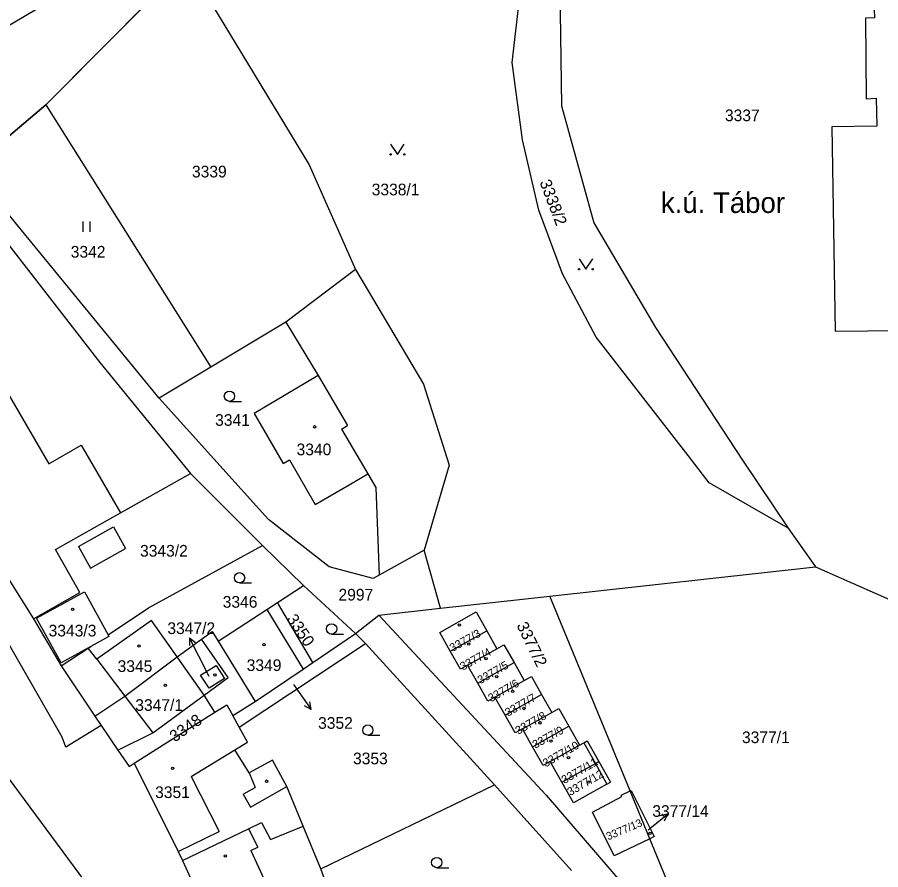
# Model space of a CAD drawing. Extents: x -738085 to -734306, y -1122197 to -1119753.
# Drawn here: x -735120.1 to -734994.5, y -1120373.5 to -1120249.4 of the extents above; entities that cross this region are included whole.
import ezdxf

# ---------------------------------------------------------------- set-up
doc = ezdxf.new("R2010")
doc.units = 0
for name, color, linetype in [('Hranice parcel', 7, 'Continuous'), ('Parcelní čísla', 7, 'Continuous'), ('Pop  PČ popisy', 7, 'Continuous'), ('SŽDC', 7, 'Continuous'), ('Vnitřní kresba', 7, 'Continuous'), ('Vrstva 1', 7, 'Continuous'), ('Vrstva 53', 7, 'Continuous'), ('Značky budov', 7, 'Continuous'), ('Značky kultur', 7, 'Continuous')]:
    doc.layers.add(name, color=color, linetype=linetype)

msp = doc.modelspace()

# ---------------------------------------------------------------- linework, layer by layer
at = {"layer": 'Hranice parcel'}
for p, q in [((-735095.46, -1120241.5), (-735115.98, -1120262.16)), ((-735115.98, -1120262.16), (-735126.91, -1120271.38)), ((-735115.98, -1120262.16), (-735091.96, -1120300.34)), ((-735070.92, -1120286.13), (-735081.05, -1120293.8)), ((-735081.05, -1120293.8), (-735091.96, -1120300.34)), ((-735091.96, -1120300.34), (-735099.51, -1120304.86)), ((-735094.95, -1120315.79), (-735084.44, -1120326.28)), ((-735007.98, -1120323.75), (-735004, -1120329.4)), ((-735084.44, -1120326.28), (-735078.49, -1120332.09)), ((-735060.91, -1120326.97), (-735067.5, -1120330.6)), ((-735058.56, -1120335.42), (-735060.91, -1120326.97)), ((-735042.66, -1120333.67), (-735004, -1120329.4)), ((-735004, -1120329.4), (-734988.44, -1120336.27)), ((-735082.29, -1120334.57), (-735078.49, -1120332.09)), ((-735078.49, -1120332.09), (-735070.91, -1120339.1)), ((-735058.56, -1120335.42), (-735042.66, -1120333.67)), ((-735030.98, -1120361.99), (-735042.66, -1120333.67)), ((-735077.11, -1120343.32), (-735082.29, -1120334.57)), ((-735067.51, -1120336.41), (-735058.56, -1120335.42)), ((-735070.91, -1120339.1), (-735067.51, -1120336.41)), ((-735117.78, -1120336.94), (-735113.76, -1120343.8)), ((-735077.11, -1120343.32), (-735070.91, -1120339.1)), ((-735069.48, -1120340.54), (-735070.91, -1120339.1)), ((-735057.13, -1120341.67), (-735051.83, -1120338.69)), ((-735051.83, -1120338.69), (-735050.36, -1120341.3)), ((-735096.87, -1120342.5), (-735093.34, -1120339.91)), ((-735087.83, -1120352.73), (-735069.48, -1120340.54)), ((-735050.7, -1120361.08), (-735069.48, -1120340.54)), ((-735113.76, -1120343.8), (-735109.82, -1120341.23)), ((-735109.82, -1120341.23), (-735109.44, -1120340.97)), ((-735054.61, -1120343.69), (-735050.36, -1120341.3)), ((-735092.93, -1120348.05), (-735096.87, -1120342.5)), ((-735113.76, -1120343.8), (-735108.84, -1120351.11)), ((-735053.14, -1120346.3), (-735054.61, -1120343.69)), ((-735053.14, -1120346.3), (-735047.84, -1120343.32)), ((-735047.84, -1120343.32), (-735046.37, -1120345.93)), ((-735050.63, -1120348.33), (-735046.37, -1120345.93)), ((-735091.37, -1120350.53), (-735092.93, -1120348.05)), ((-735049.16, -1120350.94), (-735043.86, -1120347.95)), ((-735043.86, -1120347.95), (-735042.38, -1120350.56)), ((-735049.16, -1120350.94), (-735050.63, -1120348.33)), ((-735103.15, -1120357.97), (-735091.37, -1120350.53)), ((-735046.64, -1120352.96), (-735042.38, -1120350.56)), ((-735108.84, -1120351.11), (-735107.92, -1120352.48)), ((-735087.83, -1120352.73), (-735088.77, -1120351.02)), ((-735107.92, -1120352.48), (-735105.51, -1120356.05)), ((-735045.17, -1120355.57), (-735046.64, -1120352.96)), ((-735045.17, -1120355.57), (-735039.87, -1120352.58)), ((-735039.87, -1120352.58), (-735038.32, -1120355.32)), ((-735042.59, -1120357.72), (-735038.32, -1120355.32)), ((-735040.89, -1120360.73), (-735042.59, -1120357.72)), ((-735040.89, -1120360.73), (-735036.02, -1120357.98)), ((-735075.99, -1120373.34), (-735050.7, -1120361.08)), ((-735039.5, -1120373.56), (-735050.7, -1120361.08)), ((-735028.11, -1120368.94), (-735030.98, -1120361.99)), ((-735075.99, -1120373.34), (-735078.55, -1120367.09)), ((-735019.26, -1120390.39), (-735028.11, -1120368.94)), ((-735096.09, -1120372.12), (-735092.98, -1120378.93)), ((-735075.41, -1120374.92), (-735075.99, -1120373.34))]:
    msp.add_line(p, q, dxfattribs=at)
for points in [[(-735007.98, -1120323.75), (-735019.45, -1120317.14), (-735022.52, -1120313.19), (-735035.93, -1120295.95), (-735040.81, -1120286.74), (-735044.27, -1120277.48), (-735046.62, -1120267.24), (-735048.14, -1120256), (-735046.94, -1120245.5), (-735044.72, -1120235.55), (-735040.96, -1120226.43), (-735034.02, -1120215.67), (-735028.14, -1120208.39), (-735021.59, -1120202.89), (-735007.79, -1120195.85)], [(-735008.98, -1120204.76), (-735000.64, -1120199.87), (-734997.94, -1120203.05), (-734997.43, -1120215.84), (-735002.6, -1120215.9), (-735001.92, -1120245.63), (-734995.53, -1120245.59), (-734995.39, -1120249.51), (-734996.74, -1120249.56), (-734996.6, -1120261.29), (-734995.16, -1120261.22), (-734995.08, -1120265.25), (-735001.61, -1120265.38), (-735001.13, -1120295.08), (-734986.97, -1120294.94), (-734982.61, -1120294.19)], [(-735008.98, -1120204.76), (-735028.61, -1120216.64), (-735041.23, -1120241.83), (-735040.97, -1120262.31), (-735036.25, -1120279.32), (-735027.29, -1120294.54), (-735014.62, -1120313.86), (-735007.98, -1120323.75)], [(-735095.46, -1120241.5), (-735077.67, -1120270.9), (-735070.92, -1120286.13)], [(-735138.19, -1120266.43), (-735129.75, -1120274.85), (-735122.53, -1120281.1), (-735108.15, -1120299.66), (-735094.95, -1120315.79)], [(-735099.51, -1120304.86), (-735120.4, -1120279.32), (-735126.91, -1120271.38)], [(-735107.92, -1120352.48), (-735113.07, -1120355.6), (-735113.62, -1120354.14), (-735135.26, -1120316.47), (-735148.73, -1120292.25), (-735156.12, -1120276.6)], [(-735070.92, -1120286.13), (-735061.04, -1120302.82), (-735057.28, -1120314.6), (-735060.91, -1120326.97)], [(-735081.05, -1120293.8), (-735076.37, -1120301.57), (-735085.67, -1120307.08), (-735081.46, -1120314.34), (-735080.54, -1120313.81), (-735076.77, -1120320.3), (-735071.87, -1120317.44), (-735069.13, -1120315.84), (-735067.96, -1120317.82), (-735067.5, -1120330.6)], [(-735067.5, -1120330.6), (-735068.34, -1120331.06), (-735074.75, -1120329.4), (-735083.57, -1120322.52), (-735099.51, -1120304.86)], [(-735117.78, -1120336.94), (-735111.05, -1120333.12), (-735114.58, -1120326.87), (-735105.14, -1120321.54), (-735094.95, -1120315.79)], [(-735106.92, -1120339.28), (-735101.06, -1120335.34), (-735084.44, -1120326.28)], [(-735121.6, -1120330.83), (-735117.78, -1120336.94)], [(-735109.44, -1120340.97), (-735113.77, -1120343.37), (-735117.35, -1120336.84), (-735110.36, -1120333.04), (-735106.92, -1120339.28)], [(-735093.34, -1120339.91), (-735091.78, -1120338.77), (-735090.91, -1120340.19), (-735083.83, -1120335.57), (-735082.29, -1120334.57)], [(-735067.51, -1120336.41), (-735043.2, -1120362.59), (-735019.26, -1120390.39)], [(-735057.13, -1120341.67), (-735058.67, -1120338.93), (-735053.38, -1120335.95), (-735051.83, -1120338.69)], [(-735096.87, -1120342.5), (-735100.62, -1120337.21), (-735108.56, -1120342.84), (-735109.82, -1120341.23)], [(-735106.92, -1120339.28), (-735106.8, -1120339.51), (-735109.44, -1120340.97)], [(-735092.93, -1120348.05), (-735089.44, -1120345.49), (-735093.34, -1120339.91)], [(-735040.76, -1120465.73), (-735061.72, -1120440.92), (-735081.14, -1120416.75), (-735107.98, -1120378.29), (-735135.71, -1120340.76)], [(-735054.61, -1120343.69), (-735055.66, -1120344.28), (-735057.13, -1120341.67)], [(-735050.36, -1120341.3), (-735049.32, -1120340.71), (-735047.84, -1120343.32)], [(-735108.84, -1120351.11), (-735104.5, -1120348.19), (-735096.87, -1120342.5)], [(-735088.77, -1120351.02), (-735085.52, -1120348.97), (-735078.53, -1120344.29), (-735077.11, -1120343.32)], [(-735046.37, -1120345.93), (-735045.33, -1120345.34), (-735043.86, -1120347.95)], [(-735050.63, -1120348.33), (-735051.67, -1120348.91), (-735053.14, -1120346.3)], [(-735105.51, -1120356.05), (-735100.43, -1120353.54), (-735092.93, -1120348.05)], [(-735091.37, -1120350.53), (-735089.64, -1120349.44), (-735088.77, -1120351.02)], [(-735042.38, -1120350.56), (-735041.34, -1120349.97), (-735039.87, -1120352.58)], [(-735046.64, -1120352.96), (-735047.69, -1120353.55), (-735049.16, -1120350.94)], [(-735078.55, -1120367.09), (-735080.91, -1120361.32), (-735082.99, -1120357.5), (-735086.41, -1120359.36), (-735088.49, -1120356), (-735086.65, -1120354.88), (-735087.83, -1120352.73)], [(-735042.59, -1120357.72), (-735043.63, -1120358.31), (-735045.17, -1120355.57)], [(-735038.32, -1120355.32), (-735037.71, -1120354.98), (-735036.02, -1120357.98)], [(-735105.51, -1120356.05), (-735103.85, -1120358.41), (-735103.15, -1120357.97)], [(-735103.15, -1120357.97), (-735096.75, -1120370.79), (-735096.09, -1120372.12)], [(-735036.02, -1120357.98), (-735034.33, -1120360.98), (-735039.2, -1120363.73), (-735040.89, -1120360.73)], [(-735028.11, -1120368.94), (-735033.28, -1120371.43), (-735036.46, -1120365.06), (-735032.18, -1120362.81), (-735032.27, -1120362.62), (-735030.98, -1120361.99)], [(-735030.98, -1120361.99), (-735030.83, -1120361.92), (-735027.48, -1120368.64), (-735028.11, -1120368.94)], [(-735096.09, -1120372.12), (-735086.5, -1120367.51), (-735084.59, -1120366.59), (-735083.3, -1120369.03), (-735078.55, -1120367.09)]]:
    msp.add_lwpolyline(points, dxfattribs=at)
at = {"layer": 'Pop  PČ popisy'}
for p, q in [((-735093.73, -1120342.38), (-735095.09, -1120339.71)), ((-735095.09, -1120339.71), (-735094.19, -1120340.37)), ((-735095.09, -1120339.71), (-735095.08, -1120340.83)), ((-735092.2, -1120345.34), (-735093.73, -1120342.38)), ((-735079.96, -1120346.48), (-735079.11, -1120347.68)), ((-735079.11, -1120347.68), (-735077.39, -1120350.14)), ((-735077.39, -1120350.14), (-735077.55, -1120349.03)), ((-735077.39, -1120350.14), (-735078.37, -1120349.6)), ((-735027.87, -1120367.27), (-735025.54, -1120365.38)), ((-735025.54, -1120365.38), (-735026.63, -1120365.62)), ((-735025.54, -1120365.38), (-735026, -1120366.4)), ((-735028.34, -1120367.65), (-735027.87, -1120367.27))]:
    msp.add_line(p, q, dxfattribs=at)
at = {"layer": 'SŽDC'}
for p, q in [((-735115.98, -1120262.16), (-735095.46, -1120241.5)), ((-735126.91, -1120271.38), (-735115.98, -1120262.16))]:
    msp.add_line(p, q, dxfattribs=at)
at = {"layer": 'Vnitřní kresba'}
for p, q in [((-735127.32, -1120294.17), (-735115.57, -1120314.42)), ((-735076.37, -1120301.57), (-735072.08, -1120308.82)), ((-735072.98, -1120309.35), (-735072.08, -1120308.82)), ((-735072.98, -1120309.35), (-735069.13, -1120315.84)), ((-735115.57, -1120314.42), (-735110.84, -1120311.67)), ((-735110.84, -1120311.67), (-735105.14, -1120321.54)), ((-735111.24, -1120326.41), (-735106.16, -1120323.58)), ((-735106.16, -1120323.58), (-735104.4, -1120326.73)), ((-735111.24, -1120326.41), (-735109.49, -1120329.56)), ((-735109.49, -1120329.56), (-735104.4, -1120326.73)), ((-735083.83, -1120335.57), (-735078.53, -1120344.29)), ((-735090.91, -1120340.19), (-735085.52, -1120348.97)), ((-735108.56, -1120342.84), (-735104.5, -1120348.19)), ((-735093.49, -1120345.15), (-735091.18, -1120343.74)), ((-735091.18, -1120343.74), (-735089.99, -1120345.61)), ((-735092.22, -1120347.02), (-735093.49, -1120345.15)), ((-735089.99, -1120345.61), (-735092.22, -1120347.02)), ((-735104.5, -1120348.19), (-735100.43, -1120353.54)), ((-735037.71, -1120354.98), (-735037.21, -1120354.7)), ((-735037.21, -1120354.7), (-735035.52, -1120357.7)), ((-735094.83, -1120359.87), (-735088.49, -1120356)), ((-735036.02, -1120357.98), (-735035.52, -1120357.7)), ((-735035.52, -1120357.7), (-735033.83, -1120360.7)), ((-735086.41, -1120359.36), (-735085.52, -1120361.47)), ((-735094.83, -1120359.87), (-735090.77, -1120367.87)), ((-735034.33, -1120360.98), (-735033.83, -1120360.7)), ((-735087.26, -1120362.46), (-735085.52, -1120361.47)), ((-735086.2, -1120364.33), (-735080.91, -1120361.32)), ((-735087.26, -1120362.46), (-735086.2, -1120364.33)), ((-735096.75, -1120370.79), (-735090.77, -1120367.87)), ((-735086.5, -1120367.51), (-735085.15, -1120370.19)), ((-735086.17, -1120370.66), (-735085.15, -1120370.19)), ((-735086.17, -1120370.66), (-735084.22, -1120374.85))]:
    msp.add_line(p, q, dxfattribs=at)
at = {"layer": 'Vrstva 1'}
msp.add_lwpolyline([(-735048.63, -1120207.9), (-735071.26, -1120221.19), (-735095.02, -1120235.15), (-735119.18, -1120249.35), (-735123.66, -1120251.99), (-735132.32, -1120257.08), (-735139.95, -1120261.55), (-735146.73, -1120265.54), (-735150.83, -1120267.95), (-735166.13, -1120276.92), (-735184.2, -1120287.53), (-735210.89, -1120303.2), (-735238.62, -1120319.49), (-735239.7, -1120320.12), (-735247.26, -1120324.55), (-735256.8, -1120330.14), (-735273.62, -1120340.02), (-735285.77, -1120347.18), (-735296.08, -1120353.22), (-735304.06, -1120357.75)], dxfattribs=at)
at = {"layer": 'Vrstva 53'}
msp.add_lwpolyline([(-734742.39, -1120198.31), (-734748.46, -1120195.41), (-734799.69, -1120183.7), (-734853.28, -1120170.95), (-734887.03, -1120164.91), (-734913.87, -1120162.91), (-734932.65, -1120163.73), (-734954.75, -1120168.56), (-734977.62, -1120176.17), (-734996.5, -1120184.52), (-735013.84, -1120194.15), (-735022.76, -1120201.89), (-735069.62, -1120231.25), (-735085.17, -1120235.61), (-735095.46, -1120241.5), (-735115.98, -1120262.16), (-735126.91, -1120271.38), (-735136.63, -1120262.8), (-735138.78, -1120260.72), (-735140.3, -1120259.25), (-735154.27, -1120245.72)], dxfattribs=at)
at = {"layer": 'Značky budov'}
for centre in [(-735076.88, -1120309.02), (-735112.08, -1120335.58), (-735055.83, -1120337.86), (-735084.25, -1120340.71), (-735054.44, -1120340.61), (-735102.41, -1120340.91), (-735051.93, -1120342.76), (-735091.39, -1120345.13), (-735050.38, -1120345.36), (-735098.6, -1120346.61), (-735048.06, -1120347.5), (-735046.42, -1120349.99), (-735044.08, -1120352.08), (-735042.49, -1120354.73), (-735039.93, -1120357.14), (-735097.54, -1120358.71), (-735083.86, -1120360.57), (-735037, -1120360.69), (-735028.06, -1120368.14), (-735089.85, -1120371.45)]:
    msp.add_circle(centre, 0.175, dxfattribs=at)
at = {"layer": 'Značky kultur'}
for p, q in [((-735110.54, -1120280.63), (-735110.54, -1120279.13)), ((-735109.54, -1120280.63), (-735109.54, -1120279.13)), ((-735089.27, -1120305.31), (-735087.52, -1120305.31)), ((-735087.8, -1120331.73), (-735086.05, -1120331.73)), ((-735074.4, -1120339.17), (-735072.65, -1120339.17)), ((-735069.13, -1120353.88), (-735067.38, -1120353.88)), ((-735059.11, -1120373.16), (-735057.36, -1120373.16))]:
    msp.add_line(p, q, dxfattribs=at)
for points in [[(-735065.83, -1120267.88), (-735064.83, -1120269.38), (-735063.83, -1120267.88)], [(-735038.4, -1120284.59), (-735037.4, -1120286.09), (-735036.4, -1120284.59)]]:
    msp.add_lwpolyline(points, dxfattribs=at)
for centre, radius in [((-735065.83, -1120269.38), 0.1), ((-735063.83, -1120269.38), 0.1), ((-735038.4, -1120286.09), 0.1), ((-735036.4, -1120286.09), 0.1), ((-735089.27, -1120304.56), 0.75), ((-735087.8, -1120330.98), 0.75), ((-735074.4, -1120338.42), 0.75), ((-735069.13, -1120353.13), 0.75), ((-735059.11, -1120372.41), 0.75)]:
    msp.add_circle(centre, radius, dxfattribs=at)

# ---------------------------------------------------------------- texts
at = {"layer": 'Hranice parcel'}
msp.add_text('k.ú. Tábor', height=3, dxfattribs=at).set_placement((-735026.49, -1120277.9))
at = {"layer": 'Parcelní čísla'}
for s, p in [('3337', (-735017.17, -1120264.55)), ('3339', (-735094.72, -1120272.73)), ('3338/1', (-735068.57, -1120275.34)), ('3342', (-735112.36, -1120284.4)), ('3341', (-735091.35, -1120308.87)), ('3340', (-735079.5, -1120313.15)), ('3343/2', (-735102.28, -1120327.9)), ('2997', (-735073.4, -1120334.29)), ('3346', (-735090.25, -1120335.33)), ('3343/3', (-735115.58, -1120339.51)), ('3347/2', (-735098.3, -1120339.16)), ('3345', (-735105.54, -1120344.68)), ('3349', (-735086.76, -1120344.54)), ('3347/1', (-735102.97, -1120350.34)), ('3352', (-735076.37, -1120352.95)), ('3377/1', (-735014.69, -1120355.03)), ('3353', (-735071.29, -1120358.11)), ('3351', (-735100.08, -1120363.02)), ('3377/14', (-735027.74, -1120365.76))]:
    msp.add_text(s, height=1.7, dxfattribs=at).set_placement(p)
for s, height, rotation, p in [('3338/2', 1.7, 291, (-735044.17, -1120273.42)), ('3350', 1.7, 304, (-735081.01, -1120336.97)), ('3377/2', 1.7, 296, (-735047.53, -1120337.89)), ('3377/3', 1.19, 29, (-735056.82, -1120341.79)), ('3377/4', 1.19, 29, (-735055.31, -1120344.5)), ('3377/5', 1.19, 30, (-735052.75, -1120346.47)), ('3377/6', 1.19, 30, (-735051.21, -1120349.11)), ('3377/7', 1.19, 30, (-735048.75, -1120351.2)), ('3377/8', 1.19, 30, (-735047.25, -1120353.83)), ('3348', 1.7, 35, (-735097.23, -1120354.96)), ('3377/9', 1.19, 29, (-735044.78, -1120355.87)), ('3377/10', 1.19, 30, (-735043.25, -1120358.57)), ('3377/11', 1.19, 30, (-735040.53, -1120361)), ('3377/12', 1.19, 30, (-735039.69, -1120362.74)), ('3377/13', 1.139, 23, (-735034.16, -1120369.19))]:
    msp.add_text(s, height=height, rotation=rotation, dxfattribs=at).set_placement(p)

doc.saveas('drawing.dxf')
